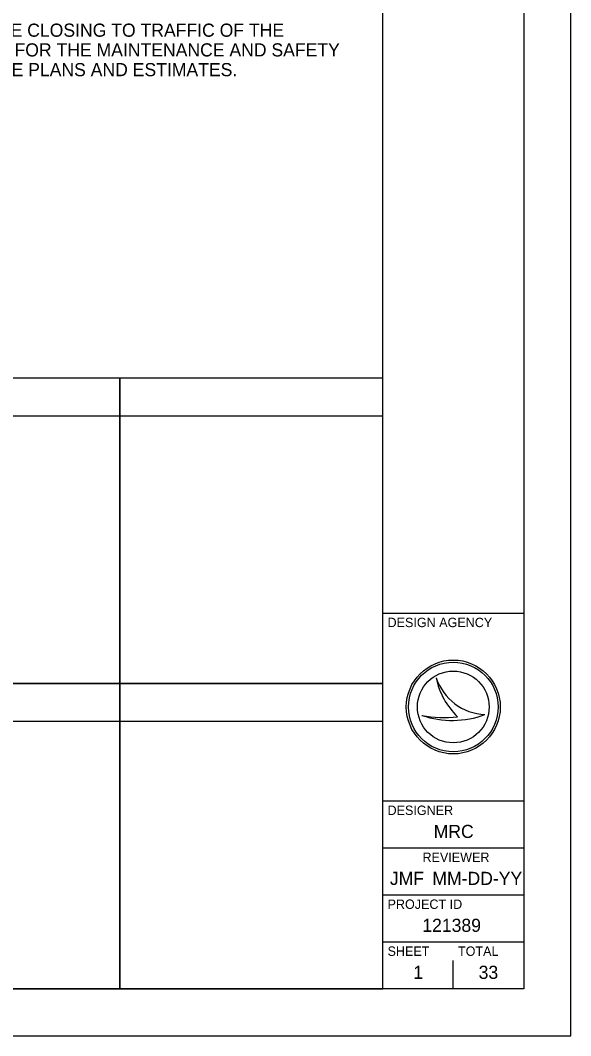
# Model space of a CAD drawing. Extents: x 0 to 34, y 0 to 22.
# Drawn here: x 28.14 to 34, y 0 to 10.81 of the extents above; entities that cross this region are included whole.
import ezdxf

# ---------------------------------------------------------------- set-up
doc = ezdxf.new("R2010")
doc.units = 0
for name, color, linetype in [('SH_Border', 7, 'Continuous'), ('SH_Cut_Line', 7, 'Continuous'), ('SH_Data', 7, 'Continuous'), ('SH_Text', 7, 'Continuous')]:
    doc.layers.add(name, color=color, linetype=linetype)

msp = doc.modelspace()

# ---------------------------------------------------------------- linework, layer by layer
at = {"layer": 'SH_Border'}
for p, q in [((32, 0.5), (32, 21.5)), ((32, 4.5), (33.5, 4.5)), ((32, 2.5), (33.5, 2.5)), ((32, 2), (33.5, 2)), ((32, 1.5), (33.5, 1.5)), ((32, 1), (33.5, 1))]:
    msp.add_line(p, q, dxfattribs=at)
msp.add_lwpolyline([(1.5, 21.5), (33.5, 21.5), (33.5, 0.5), (1.5, 0.5)], close=True, dxfattribs=at)
at = {"layer": 'SH_Cut_Line'}
msp.add_lwpolyline([(0, 0), (34, 0), (34, 22), (0, 22)], close=True, dxfattribs=at)
at = {"layer": 'SH_Data'}
for p, q in [((26.4, 6.6), (29.2, 6.6)), ((29.2, 6.6), (32, 6.6)), ((32.567, 3.81), (32.567, 3.81)), ((32.75, 3.5), (32.75, 3.5)), ((32.417, 3.41), (32.417, 3.41)), ((33.087, 3.419), (33.087, 3.419)), ((26.4, 3.35), (29.2, 3.35)), ((29.2, 3.35), (32, 3.35)), ((32.75, 0.5), (32.75, 0.8)), ((32.375, 0.675), (32.375, 0.675))]:
    msp.add_line(p, q, dxfattribs=at)
for points in [[(29.2, 7), (26.4, 7), (26.4, 3.75), (29.2, 3.75)], [(32, 7), (29.2, 7), (29.2, 3.75), (32, 3.75)], [(29.2, 3.75), (26.4, 3.75), (26.4, 0.5), (29.2, 0.5)], [(32, 3.75), (29.2, 3.75), (29.2, 0.5), (32, 0.5)]]:
    msp.add_lwpolyline(points, close=True, dxfattribs=at)
for radius in [0.5, 0.477, 0.477, 0.382]:
    msp.add_circle((32.75, 3.5), radius, dxfattribs=at)
for centre, radius, start, end in [((33.116, 3.998), 0.58, 198.9257, 198.9319), ((33.347, 3.97), 0.796, 191.6379, 191.6421), ((33.116, 3.998), 0.58, 198.9319, 267.1657), ((33.347, 3.97), 0.796, 191.6421, 226.0947), ((32.739, 4.37), 1.013, 251.4576, 290.0832), ((32.648, 4.654), 1.266, 259.4964, 259.4995), ((32.739, 4.37), 1.013, 251.4527, 251.4576), ((32.648, 4.654), 1.266, 259.4995, 276.6672)]:
    msp.add_arc(centre, radius, start, end, dxfattribs=at)

# ---------------------------------------------------------------- texts
for s, height, p in [('DESIGN AGENCY', 0.1, (32.05, 4.35)), ('DESIGNER', 0.1, (32.05, 2.35)), ('MRC', 0.14, (32.541, 2.105)), ('REVIEWER', 0.1, (32.422, 1.85)), ('JMF', 0.14, (32.075, 1.605)), ('MM-DD-YY', 0.14, (32.527, 1.605)), ('PROJECT ID', 0.1, (32.05, 1.35)), ('121389', 0.14, (32.42, 1.105)), ('SHEET', 0.1, (32.05, 0.85)), ('TOTAL', 0.1, (32.8, 0.85)), ('1', 0.14, (32.325, 0.605)), ('33', 0.14, (33.02, 0.605))]:
    msp.add_text(s, height=height, dxfattribs=at).set_placement(p)
at = {"layer": 'SH_Text'}
for s, p in [('IMPROVEMENT WILL NOT REQUIRE THE CLOSING TO TRAFFIC OF THE', (24.5, 10.636)), ('HIGHWAY AND THAT THE PROVISIONS FOR THE MAINTENANCE AND SAFETY', (24.5, 10.426)), ('OF TRAFFIC WILL BE SET FORTH IN THE PLANS AND ESTIMATES.', (24.5, 10.216))]:
    msp.add_text(s, height=0.14, dxfattribs=at).set_placement(p)

doc.saveas('drawing.dxf')
